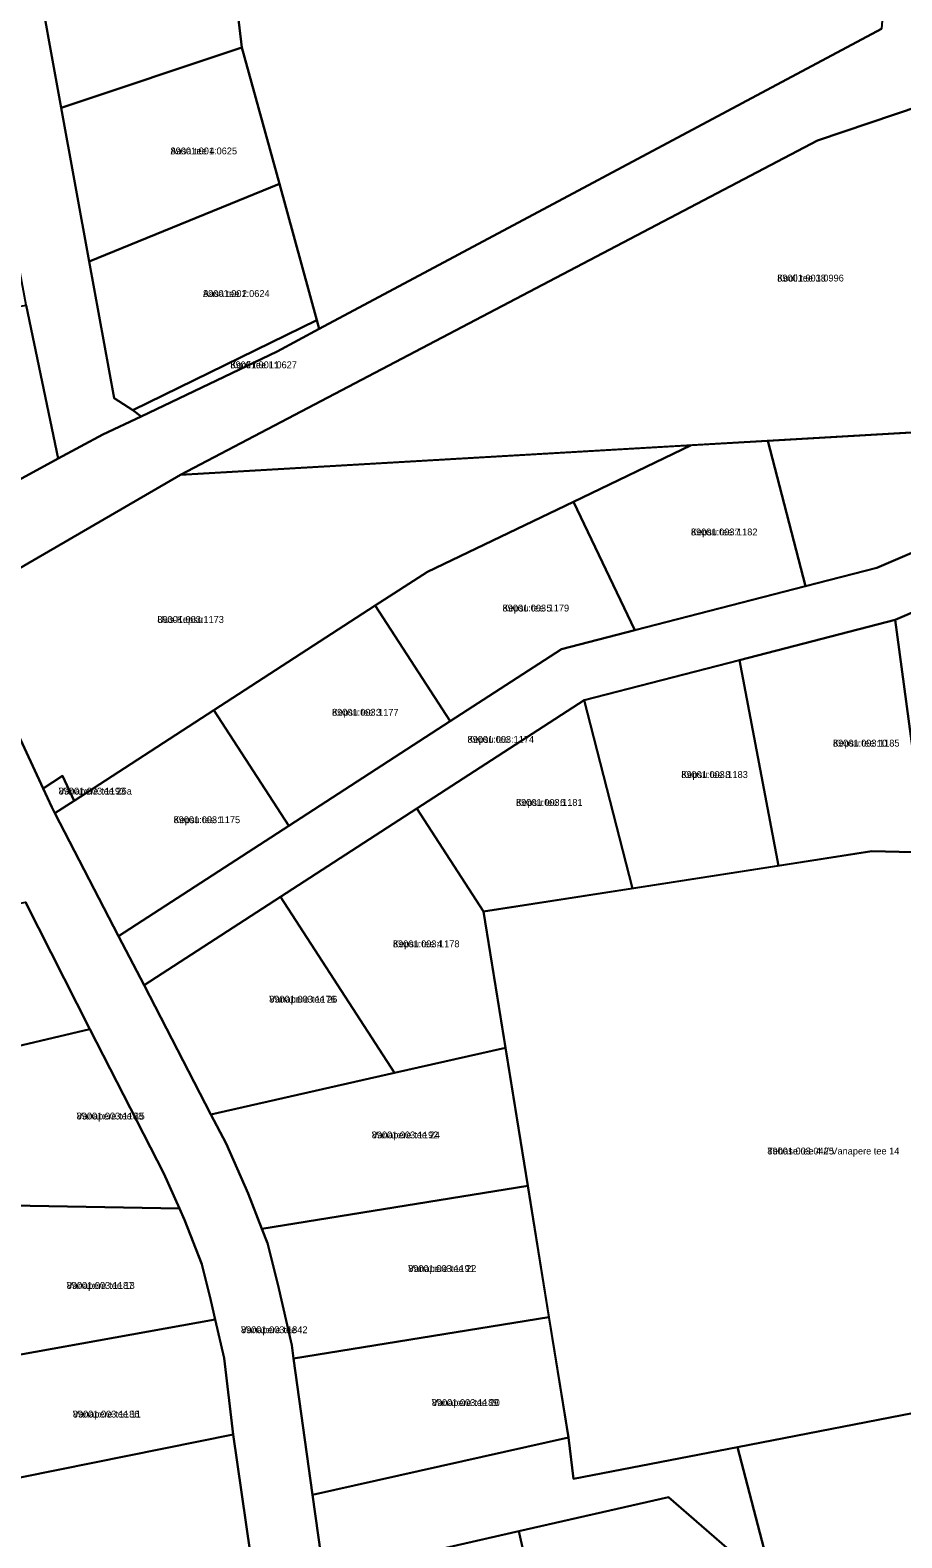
# Model space of a CAD drawing. Extents: x 526849 to 562296, y 6591741 to 6618546.
# Drawn here: x 545463.3 to 545653.3, y 6600894.1 to 6601222.5 of the extents above; entities that cross this region are included whole.
import ezdxf

# ---------------------------------------------------------------- set-up
doc = ezdxf.new("R2010")
doc.units = 0
for name, color, linetype in [('L_AADRESS', 7, 'Continuous'), ('PIIR', 7, 'Continuous'), ('TUNNUS', 7, 'Continuous')]:
    doc.layers.add(name, color=color, linetype=linetype)

msp = doc.modelspace()

# ---------------------------------------------------------------- linework, layer by layer
at = {"layer": 'PIIR'}
for points in [[(545509.48, 6601218.75), (545505.56, 6601251.79), (545543.77, 6601270.56), (545591.97, 6601294.03), (545614.78, 6601298.05), (545633.73, 6601286.89), (545642.91, 6601281.48), (545653.03, 6601275.51), (545648.79, 6601222.78), (545526.31, 6601157.4), (545525.78, 6601159.34), (545517.63, 6601189.05)], [(545470.1, 6601205.59), (545464.2, 6601238.02), (545505.56, 6601251.79), (545509.48, 6601218.75)], [(545476.2, 6601172.11), (545470.1, 6601205.59), (545509.48, 6601218.75), (545517.63, 6601189.05)], [(545496.07, 6601125.65), (545634.89, 6601198.43), (545668.62, 6601209.84), (545677.09, 6601160.57), (545681.2, 6601136.36), (545680.32, 6601136.31)], [(545481.63, 6601142.34), (545476.2, 6601172.11), (545517.63, 6601189.05), (545525.78, 6601159.34), (545485.7, 6601139.69)], [(545417.6, 6601154.3), (545435.72, 6601157.63), (545462.48, 6601162.56), (545469.47, 6601129.21), (545427.15, 6601106.18)], [(545487.54, 6601138.34), (545485.7, 6601139.69), (545525.78, 6601159.34), (545526.31, 6601157.4), (545517.17, 6601152.47)], [(545679.19, 6601136.24), (545681.98, 6601120.06), (545647.78, 6601105.4), (545632.23, 6601101.38), (545624.05, 6601133.05)], [(545624.05, 6601133.05), (545632.23, 6601101.38), (545595.1, 6601091.8), (545581.7, 6601119.76), (545607.38, 6601132.09)], [(545607.38, 6601132.09), (545581.7, 6601119.76), (545549.89, 6601104.48), (545538.53, 6601097.13), (545503.38, 6601074.35), (545472.95, 6601054.64), (545470.37, 6601060.06), (545466.15, 6601057.32), (545447.5, 6601097.42), (545496.07, 6601125.65)], [(545681.98, 6601120.06), (545684.05, 6601107.89), (545651.77, 6601094.04), (545617.89, 6601085.29), (545584.01, 6601076.54), (545547.57, 6601052.94), (545517.86, 6601033.69), (545488.15, 6601014.44), (545482.6, 6601025.15), (545519.69, 6601049.17), (545554.84, 6601071.95), (545579.12, 6601087.67), (545595.1, 6601091.8), (545632.23, 6601101.38), (545647.78, 6601105.4)], [(545581.7, 6601119.76), (545595.1, 6601091.8), (545579.12, 6601087.67), (545554.84, 6601071.95), (545538.53, 6601097.13), (545549.89, 6601104.48)], [(545684.05, 6601107.89), (545711.93, 6600944.69), (545685.77, 6600935.67), (545676.86, 6601009.8), (545658.6, 6601043.33), (545651.77, 6601094.04)], [(545538.53, 6601097.13), (545554.84, 6601071.95), (545519.69, 6601049.17), (545503.38, 6601074.35)], [(545651.77, 6601094.04), (545658.6, 6601043.33), (545646.74, 6601043.65), (545626.4, 6601040.46), (545617.89, 6601085.29)], [(545617.89, 6601085.29), (545626.4, 6601040.46), (545594.6, 6601035.52), (545584.01, 6601076.54)], [(545503.38, 6601074.35), (545519.69, 6601049.17), (545482.6, 6601025.15), (545468.74, 6601051.91), (545472.95, 6601054.64)], [(545584.01, 6601076.54), (545594.6, 6601035.52), (545562.12, 6601030.48), (545547.57, 6601052.94)], [(545388.3, 6601058.92), (545402.42, 6601041.8), (545444.64, 6601041.95), (545449.99, 6601030.09), (545462.36, 6601032.56), (545476.35, 6601004.89), (545453.55, 6600999.5), (545447.69, 6600998.76), (545442.58, 6600999.52), (545418.84, 6600996.04), (545415.06, 6601007.96), (545380.22, 6601007.48), (545368.56, 6601036.12), (545368.13, 6601039.07), (545367.72, 6601041.88)], [(545470.37, 6601060.06), (545472.95, 6601054.64), (545468.74, 6601051.91), (545468.06, 6601053.22), (545466.15, 6601057.32)], [(545547.57, 6601052.94), (545562.12, 6601030.48), (545566.9, 6601000.78), (545542.71, 6600995.33), (545517.86, 6601033.69)], [(545646.74, 6601043.65), (545658.6, 6601043.33), (545676.86, 6601009.8), (545685.77, 6600935.67), (545684.99, 6600919.29), (545663.21, 6600914.31), (545660.77, 6600922.21), (545617.44, 6600913.79), (545581.71, 6600906.94), (545580.61, 6600915.92), (545562.12, 6601030.48)], [(545517.86, 6601033.69), (545542.71, 6600995.33), (545502.72, 6600986.31), (545488.15, 6601014.44)], [(545476.35, 6601004.89), (545492.49, 6600973.43), (545495.88, 6600965.82), (545451.06, 6600966.58), (545453.55, 6600999.5)], [(545566.9, 6601000.78), (545571.75, 6600970.78), (545513.83, 6600961.38), (545510.85, 6600969.09), (545506.01, 6600979.95), (545502.72, 6600986.31), (545542.71, 6600995.33)], [(545571.75, 6600970.78), (545576.37, 6600942.14), (545520.74, 6600933.16), (545520.33, 6600936.07), (545517.31, 6600949.31), (545515.04, 6600958.24), (545513.83, 6600961.38)], [(545495.88, 6600965.82), (545496.99, 6600963.33), (545500.72, 6600953.68), (545502.73, 6600945.79), (545503.67, 6600941.66), (545438.98, 6600930.02), (545441.94, 6600965.5), (545451.06, 6600966.58)], [(545576.37, 6600942.14), (545580.61, 6600915.92), (545524.88, 6600903.41), (545520.74, 6600933.16)], [(545727.45, 6600849.47), (545636.38, 6600841.14), (545617.44, 6600913.79), (545660.77, 6600922.21), (545663.21, 6600914.31), (545684.99, 6600919.29), (545685.77, 6600935.67), (545713.85, 6600945.34)], [(545503.67, 6600941.66), (545505.59, 6600933.23), (545507.54, 6600916.6), (545453.92, 6600905.74), (545451.89, 6600901.13), (545436.36, 6600898.87), (545438.98, 6600930.02)], [(545436.36, 6600898.87), (545451.89, 6600901.13), (545453.92, 6600905.74), (545507.54, 6600916.6), (545522.5, 6600813.01), (545458.06, 6600799.88), (545450.9, 6600805.53), (545446.05, 6600804.87), (545407.32, 6600825.01), (545411.94, 6600838.8), (545418.48, 6600856.41), (545427.58, 6600866.61)], [(545524.75, 6600885.26), (545546.31, 6600890.17), (545547.15, 6600877.36), (545550.79, 6600870.75), (545574.2, 6600876.09), (545569.82, 6600895.53), (545602.4, 6600902.96), (545616.83, 6600890.43), (545620.67, 6600867.96), (545623.29, 6600846.15), (545617.64, 6600834.72), (545539.69, 6600818.94), (545534.41, 6600824.46), (545529.43, 6600847.87)], [(545546.31, 6600890.17), (545569.82, 6600895.53), (545574.2, 6600876.09), (545550.79, 6600870.75), (545547.15, 6600877.36)]]:
    msp.add_lwpolyline(points, close=True, dxfattribs=at)
for points in [[(545464.2, 6601238.02), (545470.1, 6601205.59), (545476.2, 6601172.11), (545481.63, 6601142.34), (545485.7, 6601139.69), (545487.54, 6601138.34), (545479.21, 6601134.38), (545469.47, 6601129.21), (545462.48, 6601162.56), (545454.53, 6601204.85), (545448.75, 6601237.34)], [(545137.32, 6600894.8), (545177.09, 6600903.41), (545193.31, 6600916.82), (545208.72, 6600929.55), (545224.19, 6600942.33), (545239.69, 6600955.14), (545270.56, 6600980.66), (545293.04, 6600999.24), (545316.79, 6601018.87), (545331.58, 6601031.1), (545347.2, 6601044), (545362.79, 6601056.89), (545378.81, 6601070.13), (545393.68, 6601082.42), (545414.7, 6601099.79), (545427.15, 6601106.18), (545469.47, 6601129.21), (545479.21, 6601134.38), (545487.54, 6601138.34), (545517.17, 6601152.47), (545526.31, 6601157.4), (545648.79, 6601222.78)], [(545668.62, 6601209.84), (545634.89, 6601198.43), (545496.07, 6601125.65), (545447.5, 6601097.42), (545433.57, 6601090.64), (545428.1, 6601091.8), (545414.55, 6601080.6), (545413.53, 6601081.87), (545387.67, 6601059.72), (545388.3, 6601058.92), (545367.72, 6601041.88), (545355.5, 6601031.77), (545298.64, 6600984.92), (545262.65, 6600954.73), (545209.63, 6600911.51), (545205.01, 6600893.85), (545199.46, 6600900.86), (545194, 6600897.2), (545195.69, 6600891.85), (545160.32, 6600884.19), (545153.37, 6600882.68), (545138.28, 6600879.43)], [(545447.5, 6601097.42), (545466.15, 6601057.32), (545468.06, 6601053.22), (545468.74, 6601051.91), (545482.6, 6601025.15), (545488.15, 6601014.44), (545502.72, 6600986.31), (545506.01, 6600979.95), (545510.85, 6600969.09), (545513.83, 6600961.38), (545515.04, 6600958.24), (545517.31, 6600949.31), (545520.33, 6600936.07), (545520.74, 6600933.16), (545524.88, 6600903.41), (545527.32, 6600885.85)], [(545522.5, 6600813.01), (545507.54, 6600916.6), (545505.59, 6600933.23), (545503.67, 6600941.66), (545502.73, 6600945.79), (545500.72, 6600953.68), (545496.99, 6600963.33), (545495.88, 6600965.82), (545492.49, 6600973.43), (545476.35, 6601004.89), (545462.36, 6601032.56)], [(545669.41, 6600832.52), (545620.42, 6600822.9), (545540.9, 6600807.29), (545539.69, 6600818.94), (545617.64, 6600834.72), (545623.29, 6600846.15), (545620.67, 6600867.96), (545616.83, 6600890.43), (545602.4, 6600902.96), (545569.82, 6600895.53), (545546.31, 6600890.17), (545527.32, 6600885.85), (545524.88, 6600903.41), (545580.61, 6600915.92), (545581.71, 6600906.94), (545617.44, 6600913.79), (545636.38, 6600841.14), (545727.45, 6600849.47)]]:
    msp.add_lwpolyline(points, dxfattribs=at)

# ---------------------------------------------------------------- texts
at = {"layer": 'L_AADRESS'}
for s, p in [('Aasa tee 4', (545493.92, 6601195.43)), ('Kooli tee 18', (545626.11, 6601167.74)), ('Aasa tee 2', (545501.01, 6601164.37)), ('Kooli tee L1', (545506.96, 6601148.84)), ('Kepsu tee 7', (545607.3, 6601112.43)), ('Kepsu tee 5', (545566.26, 6601095.86)), ('Uus-Kepsu', (545491.05, 6601093.37)), ('Kepsu tee 3', (545529.11, 6601073.15)), ('Kepsu tee', (545558.63, 6601067.25)), ('Kepsu tee 10', (545638.25, 6601066.43)), ('Kepsu tee 8', (545605.2, 6601059.59)), ('Vanapere tee 26a', (545469.55, 6601055.98)), ('Kepsu tee 6', (545569.2, 6601053.51)), ('Kepsu tee 1', (545494.59, 6601049.75)), ('Kepsu tee 4', (545542.38, 6601022.71)), ('Vanapere tee 26', (545515.43, 6601010.65)), ('Vanapere tee 15', (545473.47, 6600985.2)), ('Vanapere tee 24', (545537.76, 6600981.08)), ('Tehase tee 4 // Vanapere tee 14', (545623.95, 6600977.58)), ('Vanapere tee 22', (545545.71, 6600951.97)), ('Vanapere tee 13', (545471.3, 6600948.3)), ('Vanapere tee', (545509.27, 6600938.65)), ('Vanapere tee 20', (545550.84, 6600922.78)), ('Vanapere tee 11', (545472.63, 6600920.27))]:
    msp.add_text(s, height=1.5, dxfattribs=at).set_placement(p)
at = {"layer": 'TUNNUS'}
for s, p in [('89001:001:0625', (545493.92, 6601195.43)), ('89001:003:0996', (545626.11, 6601167.74)), ('89001:001:0624', (545501.01, 6601164.37)), ('89001:001:0627', (545506.96, 6601148.84)), ('89001:003:1182', (545607.3, 6601112.43)), ('89001:003:1179', (545566.26, 6601095.86)), ('89001:003:1173', (545491.05, 6601093.37)), ('89001:003:1177', (545529.11, 6601073.15)), ('89001:003:1174', (545558.63, 6601067.25)), ('89001:003:1185', (545638.25, 6601066.43)), ('89001:003:1183', (545605.2, 6601059.59)), ('89001:003:1193', (545469.55, 6601055.98)), ('89001:003:1181', (545569.2, 6601053.51)), ('89001:003:1175', (545494.59, 6601049.75)), ('89001:003:1178', (545542.38, 6601022.71)), ('89001:003:1176', (545515.43, 6601010.65)), ('89001:003:1188', (545473.47, 6600985.2)), ('89001:003:1192', (545537.76, 6600981.08)), ('89001:003:0425', (545623.95, 6600977.58)), ('89001:003:1191', (545545.71, 6600951.97)), ('89001:003:1187', (545471.3, 6600948.3)), ('89001:003:1842', (545509.27, 6600938.65)), ('89001:003:1189', (545550.84, 6600922.78)), ('89001:003:1186', (545472.63, 6600920.27))]:
    msp.add_text(s, height=1.5, dxfattribs=at).set_placement(p)

doc.saveas('drawing.dxf')
